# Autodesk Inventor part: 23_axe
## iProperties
Shininess: 31.0
Length Units: 11269
Angle Units: 11279
Time Units: 11290
Mass Units: 11283
Length Display Precision: 3
Angle Display Precision: 2
Compacted: True
Created: 2002-11
Part Number: 23_axe
Material: Par défaut
Document SubType Name: Modélisation
Designer: FIEVET
Density: 0.0
Volumn: 0.0
Area: 0.0
PropertySet Name: Model Information
Control State: 0
Master: False
Checked Out: False
Author: FIEVET
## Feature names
1. Révolution1 [Revolution]
